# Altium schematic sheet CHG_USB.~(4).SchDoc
size A; SheetNumber: 1; SheetTotal: 1
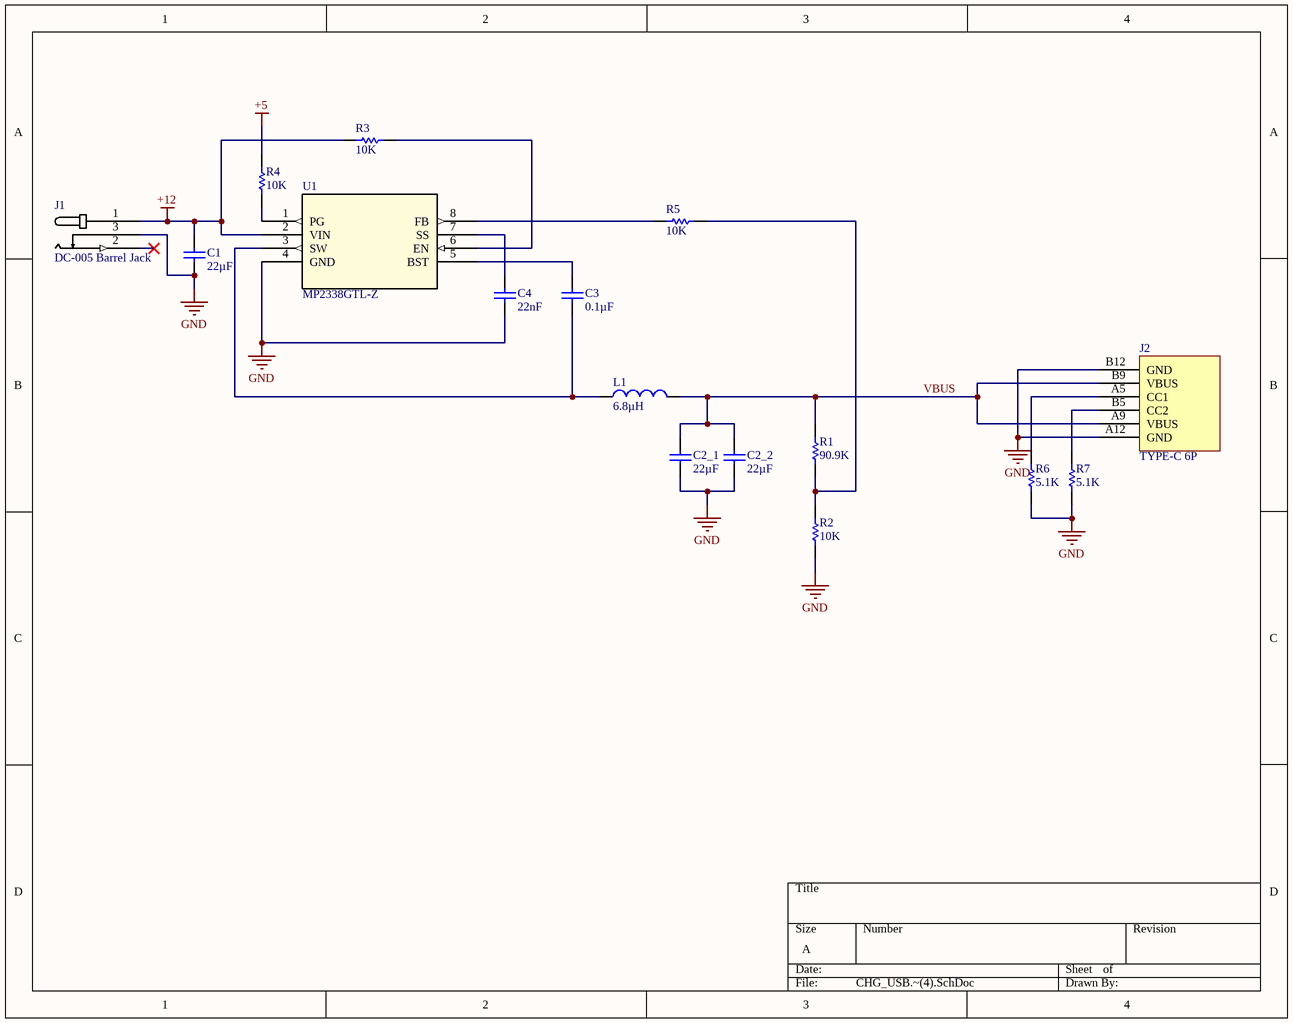
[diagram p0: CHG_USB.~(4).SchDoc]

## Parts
C1  value 22µF  (hidden comment: Capacitor)
C2_1  value 22µF  (hidden comment: Capacitor)
C2_2  value 22µF  (hidden comment: Capacitor)
C3  value 0.1µF  (hidden comment: Capacitor)
C4  value 22nF  (hidden comment: Capacitor)
J1  DC-005 Barrel Jack
J2  TYPE-C 6P
L1  value 6.8µH  (hidden comment: Inductor)
R1  value 90.9K  (hidden comment: Resistor)
R2  value 10K  (hidden comment: Resistor)
R3  value 10K  (hidden comment: Resistor)
R4  value 10K  (hidden comment: Resistor)
R5  value 10K  (hidden comment: Resistor)
R6  value 5.1K  (hidden comment: Resistor)
R7  value 5.1K  (hidden comment: Resistor)
U1  MP2338GTL-Z

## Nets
+5: R4.2
+12: C1.2 J1.1(VIN) R3.1 U1.2(VIN)
GND: C1.1 C2_1.1 C2_2.1 C4.1 J1.3(GND) J2.A12(GND) J2.B12(GND) R2.1 R6.1 R7.1 U1.4(GND)
VBUS: C2_1.2 C2_2.2 J2.A9(VBUS) J2.B9(VBUS) L1.2 R1.2
NetC3_1: C3.1 L1.1 U1.3(SW)
NetC3_2: C3.2 U1.5(BST)
NetC4_2: C4.2 U1.7(SS)
NetJ2_A5: J2.A5(CC1) R6.2
NetJ2_B5: J2.B5(CC2) R7.2
NetR1_1: R1.1 R2.2 R5.2
NetR3_2: R3.2 U1.6(EN)
NetR4_1: R4.1 U1.1(PG)
NetR5_1: R5.1 U1.8(FB)

Not connected (* = marked no-connect by the designer): J1 2(SW)*

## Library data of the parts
C1 C2_1 C2_2 C3 C4 = Capacitor: SimulationGenericComponent: True
J1 = DC-005 Barrel Jack: Barrel Jack to simplify PCB complexity
L1 = Inductor: SimulationGenericComponent: True
R1-R7 = Resistor: TC1: 0; SimulationGenericComponent: True
U1 = MP2338GTL-Z: MP2338 IC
